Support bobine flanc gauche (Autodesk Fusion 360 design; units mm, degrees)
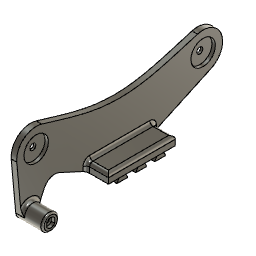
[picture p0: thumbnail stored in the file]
sketch "Esquisse1" plane through (0, 0, 0) normal (1, 0, 0) x axis (0, 1, 0)
  line L1 (30, 3.8) -> (-30, 3.8)
  line L2 (0, 13.257) -> (0, 0)
  line L3 (-4.9, 0) -> (-2.9, 3.8)
  line L4 (4.9, 0) -> (2.9, 3.8)
  line L5 (-21.9, 0) -> (-19.9, 3.8)
  line L6 (-12.1, 0) -> (-14.1, 3.8)
  line L7 (12.1, 0) -> (14.1, 3.8)
  line L8 (21.9, 0) -> (19.9, 3.8)
  line L9 (-12.1, 0) -> (-21.9, 0)
  line L10 (4.9, 0) -> (-4.9, 0)
  line L11 (21.9, 0) -> (12.1, 0)
  line L12 (75, 43.8) -> (-75, 43.8)
  line L13 (82.3227, 27.9057) -> (30, 3.8)
  line L14 (-82.3227, 27.9057) -> (-30, 3.8)
  curve K1 (70.0046, 60.5719) -> (-70.0046, 60.5719)
  curve K2 (14.2216, 45.8) -> (-14.2216, 45.8)
  line L15 (-88.3648, -1.8881) -> (-92.4262, 42.1945)
  line L16 (-63.2728, 19.1292) -> (-74.0846, -4.3383)
  line L17 (-30, 11.8) -> (-30, 3.8)
  line L18 (30, 11.8) -> (30, 3.8)
  line L19 (30, 11.8) -> (-30, 11.8)
  circle C1 centre (-75, 43.8) radius 2.7
  circle C2 centre (-75, 43.8) radius 8
  circle C3 centre (-75, 43.8) radius 17.5
  circle C4 centre (75, 43.8) radius 2.7
  circle C5 centre (75, 43.8) radius 8
  circle C6 centre (75, 43.8) radius 17.5
  circle C7 centre (0, 121.511) radius 100
  circle C8 centre (-80.8964, -1.2) radius 1.7
  circle C9 centre (-80.8964, -1.2) radius 7.5
  circle C10 centre (-80.8964, -1.2) radius 3.5
  point P1 (0, 0)
  point P4 (0, 0)
  point P6 (-2.9, 3.8)
  point P7 (-4.9, 0)
  point P8 (2.9, 3.8)
  point P9 (4.9, 0)
  point P18 (-75, 43.8)
  point P20 (-75, 43.8)
  point P27 (82.3227, 27.9057)
  point P28 (-82.3227, 27.9057)
  point P29 (-70.0046, 60.5719)
  point P31 (70.0046, 60.5719)
  point P30 (0, 45.8)
  point P36 (-92.4262, 42.1945)
  point P37 (-88.3648, -1.8881)
  point P38 (-74.0846, -4.3383)
  point P39 (-63.2728, 19.1292)
  point P19 (75, 43.8)
  point P35 (-80.8964, -1.2)
  point P2 (-30, 3.8)
  point P3 (30, 3.8)
  horizontal L9
  parallel L1 L9
  coincident P1 P4
  perpendicular L2 L9
  coincident L1 P6
  coincident P7 L9
  symmetric L2 P6 P8
  symmetric L2 P7 P9
  coincident P1 L9
  collinear L9 L10
  collinear L10 L11
  horizontal L12
  coincident P18 P20
  concentric C1 C2
  concentric C2 C3
  symmetric L2 C1 C4
  symmetric L2 C2 C5
  symmetric L2 C3 C6
  tangent C2 C7
  tangent C5 C7
  coincident C6 P27
  tangent C6 L13
  coincident C3 P28
  tangent C3 L14
  coincident C3 P29
  coincident C6 P31
  tangent C6 K1
  tangent C3 K1
  midpoint P30 K2
  horizontal K2
  concentric C8 C9
  coincident C3 P36
  coincident C9 P37
  coincident C9 P38
  coincident L14 P39
  perpendicular L14 L16
  tangent C9 L16
  tangent C9 L15
  tangent C3 L15
  perpendicular L1 L17
  perpendicular L1 L18
  concentric C8 C10
  dimension "d2" distance L1 L9 = 3.8
  dimension "d3" distance L2 P6 = 2.9
  dimension "d4" distance L2 P7 = 4.9
  dimension "d9" distance P18 P19 = 150
  dimension "d10" distance P1 P18 = 75
  dimension "d11" diameter C1 = 5.4
  dimension "d12" diameter C2 = 16
  dimension "d13" diameter C3 = 35
  dimension "d14" diameter C7 = 200
  dimension "d15" distance L1 L12 = 40
  dimension "d16" distance L1 P30 = 42
  dimension "d17" diameter C8 = 3.4
  dimension "d19" diameter C9 = 15
  dimension "d20" distance L1 P35 = 5
  dimension "d23" distance P2 P3 = 60
  dimension "d25" distance P1 L17 = 30
  dimension "d26" distance L1 L19 = 8
  dimension "d27" angle L14 L15 = 60
  dimension "d48" diameter C10 = 7
  dimension "d7" R-Pattern1-uDistance = 17
  dimension "d8" R-Pattern1-vDistance = 0
extrude "Extrusion1" new body sketch "Esquisse1" profile of C1 C3 C4 C6 L13 L14 K1 C8 C9 L15 L16 L17 L18 L19 along normal blind 5
extrude "Extrusion2" add sketch "Esquisse1" profile of L1 L17 L18 L19 along normal blind 25
sketch "Esquisse2" plane through (5, 0, 0) normal (1, 0, 0) x axis (0, 1, 0)
  line L1 (-30, 11.8) -> (-30, 3.8)
  line L2 (30, 11.8) -> (-30, 11.8)
  line L3 (30, 3.8) -> (30, 11.8)
  line L4 (82.3227, 27.9057) -> (30, 3.8)
  curve K1 (-70.0046, 60.5719) -> (70.0046, 60.5719)
  line L5 (-88.3648, -1.8881) -> (-92.4262, 42.1945)
  line L6 (-63.2728, 19.1292) -> (-74.0846, -4.3383)
  line L7 (-30, 3.8) -> (-63.2728, 19.1292)
  circle C1 centre (-80.8964, -1.2) radius 1.7
  circle C2 centre (-75, 43.8) radius 2.7
  circle C3 centre (75, 43.8) radius 2.7
  arc A1 centre (75, 43.8) radius 17.5 clockwise from (70.0046, 60.5719) to (82.3227, 27.9057)
  arc A2 centre (-75, 43.8) radius 17.5 clockwise from (-92.4262, 42.1945) to (-70.0046, 60.5719)
  arc A3 centre (-80.8964, -1.2) radius 7.5 clockwise from (-74.0846, -4.3383) to (-88.3648, -1.8881)
  circle C4 centre (-75, 43.8) radius 11
  circle C5 centre (75, 43.8) radius 11
  circle C6 centre (-80.8964, -1.2) radius 7.5
  concentric C2 C4
  concentric C3 C5
  concentric C1 C6
  dimension "d34" diameter C4 = 22
  dimension "d35" diameter C5 = 22
  dimension "d38" diameter C6 = 15
extrude "Extrusion3" cut sketch "Esquisse2" profile of C2 C3 C4 C5 against normal blind 3
extrude "Extrusion4" add sketch "Esquisse2" profile of C1 A3 C6 along normal blind 19
sketch "Esquisse3" plane through (24, 0, 0) normal (1, 0, 0) x axis (0, 1, 0)
  line L1 (-84.3962, 0.9358) -> (-84.3962, -3.3358)
  line L2 (-77.3962, -3.335) -> (-77.3962, 0.935)
  circle C1 centre (-80.8964, -1.2) radius 1.7
  circle C2 centre (-80.8964, -1.2) radius 7.5
  circle C3 centre (-80.8964, -1.2) radius 4.1
  point P2 (-80.8964, -1.2)
  point P4 (-80.8964, -1.2)
  point P5 (-84.3962, -3.3358)
  point P6 (-84.3962, 0.9358)
  point P7 (-77.3962, 0.935)
  point P8 (-77.3962, -3.335)
  concentric C1 C3
  parallel L1 L2
  coincident P2 P4
  coincident C3 P5
  coincident C3 P6
  coincident C3 P7
  coincident C3 P8
  vertical L1
  dimension "d41" diameter C3 = 8.2
  dimension "d44" distance L1 L2 = 7
  dimension "d45" distance P7 P8 = 4.27
extrude "Extrusion5" cut sketch "Esquisse3" profile of C1 C3 L1 L2 against normal blind 3
extrude "Extrusion6" cut sketch "Esquisse1" profile of C8 C10 along normal blind 17.5
fillet "Congé2" radius 1.5
fillet "Congé3" radius 3
fillet "Congé4" radius 10
fillet "Congé5" radius 3
fillet "Congé6" radius 3
extrude "Extrusion8" add sketch "Esquisse1" profile of L11 L1 L3 L4 L5 L6 L7 L8 along normal blind 24.5
sketch "Esquisse5" plane through (0, 0, 0) normal (0, 0, -1) x axis (1, 0, 0)
  line L1 (0, -4.9) -> (0, 4.9)
  line L2 (24.5, -4.9) -> (0, -4.9)
  line L3 (24.5, 4.9) -> (24.5, -4.9)
  line L4 (0, 4.9) -> (24.5, 4.9)
  circle C1 centre (12.5, 0) radius 1.4
  point P6 (12.5, 0)
  dimension "d68" diameter C1 = 2.8
  dimension "d69" distance L1 P6 = 12.5
  dimension "d70" distance L4 P6 = 4.9
extrude "Extrusion9" cut sketch "Esquisse5" profile of C1 against normal blind 10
